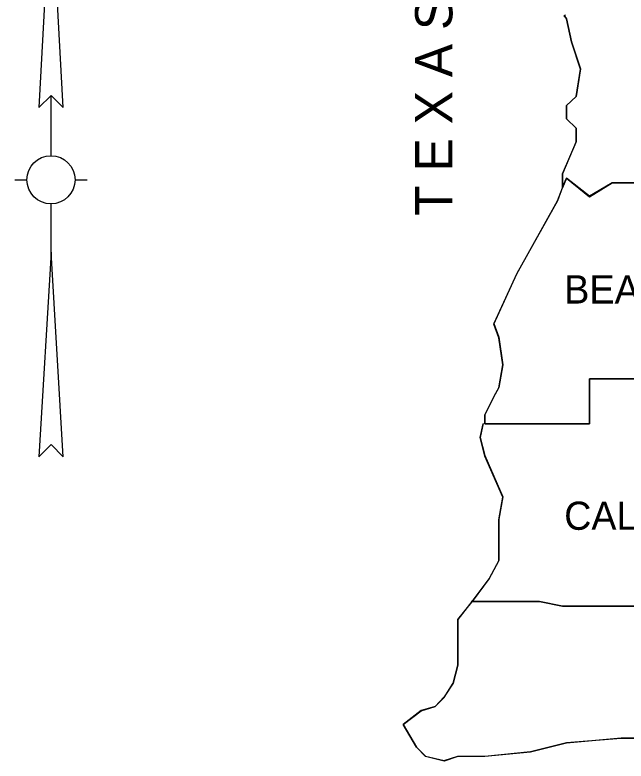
# Model space of a CAD drawing. Extents: x 0.19 to 2.82, y 0.04 to 1.79.
# Drawn here: x 2.1584 to 2.26, y 1.47 to 1.594 of the extents above; entities that cross this region are included whole.
import ezdxf

# ---------------------------------------------------------------- set-up
doc = ezdxf.new("R2010")
doc.units = 0
for name, color, linetype in [('Dist07', 7, 'Continuous'), ('Dist08', 7, 'Continuous'), ('Standard Info', 7, 'Continuous')]:
    doc.layers.add(name, color=color, linetype=linetype)

msp = doc.modelspace()

# ---------------------------------------------------------------- linework, layer by layer
at = {"layer": 'Dist07'}
msp.add_line((2.23649, 1.5275), (2.23649, 1.526), dxfattribs=at)
for points in [[(2.30232, 1.56758), (2.30157, 1.56533), (2.28032, 1.56458), (2.27965, 1.56608), (2.25765, 1.56608), (2.2539, 1.56383), (2.25007, 1.56683), (2.2494, 1.56533)], [(2.2494, 1.56533), (2.24857, 1.56308)], [(2.24857, 1.56308), (2.24182, 1.551), (2.23799, 1.54267), (2.23882, 1.54042), (2.23949, 1.53583), (2.23882, 1.53208), (2.23799, 1.53058), (2.23649, 1.5275), (2.23649, 1.52742)], [(2.23624, 1.52608), (2.23574, 1.52375), (2.23649, 1.52075), (2.23949, 1.51392), (2.23882, 1.51017), (2.23882, 1.50333), (2.23724, 1.50033), (2.2344, 1.4965)], [(2.23432, 1.4965), (2.23199, 1.4935)], [(2.23199, 1.4935), (2.23199, 1.49275), (2.23199, 1.489), (2.23199, 1.4875), (2.23199, 1.48592), (2.23124, 1.48292), (2.22974, 1.48067), (2.22824, 1.47908), (2.2259, 1.47842), (2.2229, 1.47608), (2.22515, 1.47233), (2.22665, 1.47083), (2.22974, 1.47008), (2.23199, 1.47083), (2.23649, 1.47083), (2.24407, 1.47158), (2.25007, 1.47308), (2.25915, 1.47383), (2.26824, 1.47383)]]:
    msp.add_lwpolyline(points, dxfattribs=at)
at = {"layer": 'Dist08'}
for points in [[(2.24965, 1.59392), (2.25007, 1.59333), (2.2509, 1.5895), (2.2524, 1.585), (2.25165, 1.58042), (2.25007, 1.57892), (2.25007, 1.57667), (2.25165, 1.57517), (2.25165, 1.57292), (2.2494, 1.56758), (2.2494, 1.56533)], [(2.2494, 1.56533), (2.25007, 1.56683), (2.2539, 1.56383), (2.25765, 1.56608), (2.27965, 1.56608), (2.28032, 1.56458), (2.30157, 1.56533), (2.30232, 1.56758)]]:
    msp.add_lwpolyline(points, dxfattribs=at)
at = {"layer": 'Standard Info'}
for p, q in [((2.1644, 1.61657), (2.1624, 1.57857)), ((2.1664, 1.57857), (2.1644, 1.61657)), ((2.24965, 1.59383), (2.2499, 1.594)), ((2.1624, 1.57857), (2.1644, 1.58057)), ((2.1644, 1.57057), (2.1644, 1.58057)), ((2.1644, 1.58057), (2.1664, 1.57857)), ((2.1584, 1.56657), (2.1604, 1.56657)), ((2.1684, 1.56657), (2.1704, 1.56657)), ((2.1644, 1.55457), (2.1644, 1.56257)), ((2.1644, 1.55457), (2.1624, 1.52057)), ((2.1664, 1.52057), (2.1644, 1.55457)), ((2.23649, 1.526), (2.23649, 1.5275)), ((2.1624, 1.52057), (2.1644, 1.52257)), ((2.1644, 1.52257), (2.1664, 1.52057))]:
    msp.add_line(p, q, dxfattribs=at)
for points in [[(2.2494, 1.56525), (2.2494, 1.56758), (2.25165, 1.57283), (2.25165, 1.57517), (2.25007, 1.57667), (2.25007, 1.57892), (2.25165, 1.58042), (2.2524, 1.58492), (2.2509, 1.5895), (2.25007, 1.59333), (2.24965, 1.59383)], [(2.30232, 1.56758), (2.30157, 1.56525), (2.28032, 1.56458), (2.27965, 1.56608), (2.25765, 1.56608), (2.2539, 1.56375), (2.25007, 1.56683), (2.2494, 1.56525)], [(2.2494, 1.56525), (2.25007, 1.56683), (2.2539, 1.56375), (2.25765, 1.56608), (2.27965, 1.56608), (2.28032, 1.56458), (2.2909, 1.56492)], [(2.24857, 1.56308), (2.2494, 1.56525)], [(2.23649, 1.52733), (2.23649, 1.5275), (2.23799, 1.5305), (2.23882, 1.532), (2.23949, 1.53583), (2.23882, 1.54033), (2.23799, 1.54258), (2.24182, 1.55092), (2.24857, 1.56308)], [(2.2794, 1.526), (2.26149, 1.526), (2.26149, 1.5335), (2.2539, 1.5335), (2.2539, 1.526), (2.23649, 1.526)], [(2.23649, 1.526), (2.2539, 1.526), (2.2539, 1.5335), (2.26149, 1.5335), (2.26149, 1.526), (2.2794, 1.526)], [(2.2344, 1.4965), (2.23724, 1.50025), (2.23882, 1.50325), (2.23882, 1.51008), (2.23949, 1.51383), (2.23649, 1.52067), (2.23574, 1.52375), (2.23624, 1.526)], [(2.23199, 1.4935), (2.23432, 1.49642)], [(2.2894, 1.495), (2.28032, 1.495), (2.27965, 1.49575), (2.2494, 1.49575), (2.24557, 1.4965), (2.23424, 1.4965)], [(2.23424, 1.4965), (2.24557, 1.4965), (2.2494, 1.49575), (2.27965, 1.49575), (2.28032, 1.495), (2.3099, 1.495)], [(2.26824, 1.47383), (2.25915, 1.47383), (2.25007, 1.473), (2.24407, 1.4715), (2.23649, 1.47075), (2.23199, 1.47075), (2.22974, 1.47), (2.22665, 1.47075), (2.22515, 1.47233), (2.2229, 1.47608), (2.2259, 1.47833), (2.22824, 1.47908), (2.22974, 1.48058), (2.23124, 1.48292), (2.23199, 1.48592), (2.23199, 1.48742), (2.23199, 1.48892), (2.23199, 1.49267), (2.23199, 1.4935)]]:
    msp.add_lwpolyline(points, dxfattribs=at)
msp.add_circle((2.16439, 1.56657), 0.004, dxfattribs=at)

# ---------------------------------------------------------------- texts
msp.add_text('T E X A S', height=0.0062, rotation=90, dxfattribs=at).set_placement((2.23111, 1.56058))
for s, height, p in [('BEAUREGARD', 0.0047, (2.24968, 1.54601)), ('CALCASIEU', 0.004679, (2.24969, 1.50842))]:
    msp.add_text(s, height=height, dxfattribs=at).set_placement(p)

doc.saveas('drawing.dxf')
